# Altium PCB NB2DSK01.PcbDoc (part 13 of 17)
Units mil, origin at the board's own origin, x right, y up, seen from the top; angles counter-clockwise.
Board outline 11815 x 6500.03 mil, 8 copper layers (Top Layer, MidLayer1, MidLayer2, GND, PWR, MidLayer3, MidLayer4, Bottom Layer), stack 74.62 mil thick; 798 components, 1002 nets, 3927 pads, 3182 vias.
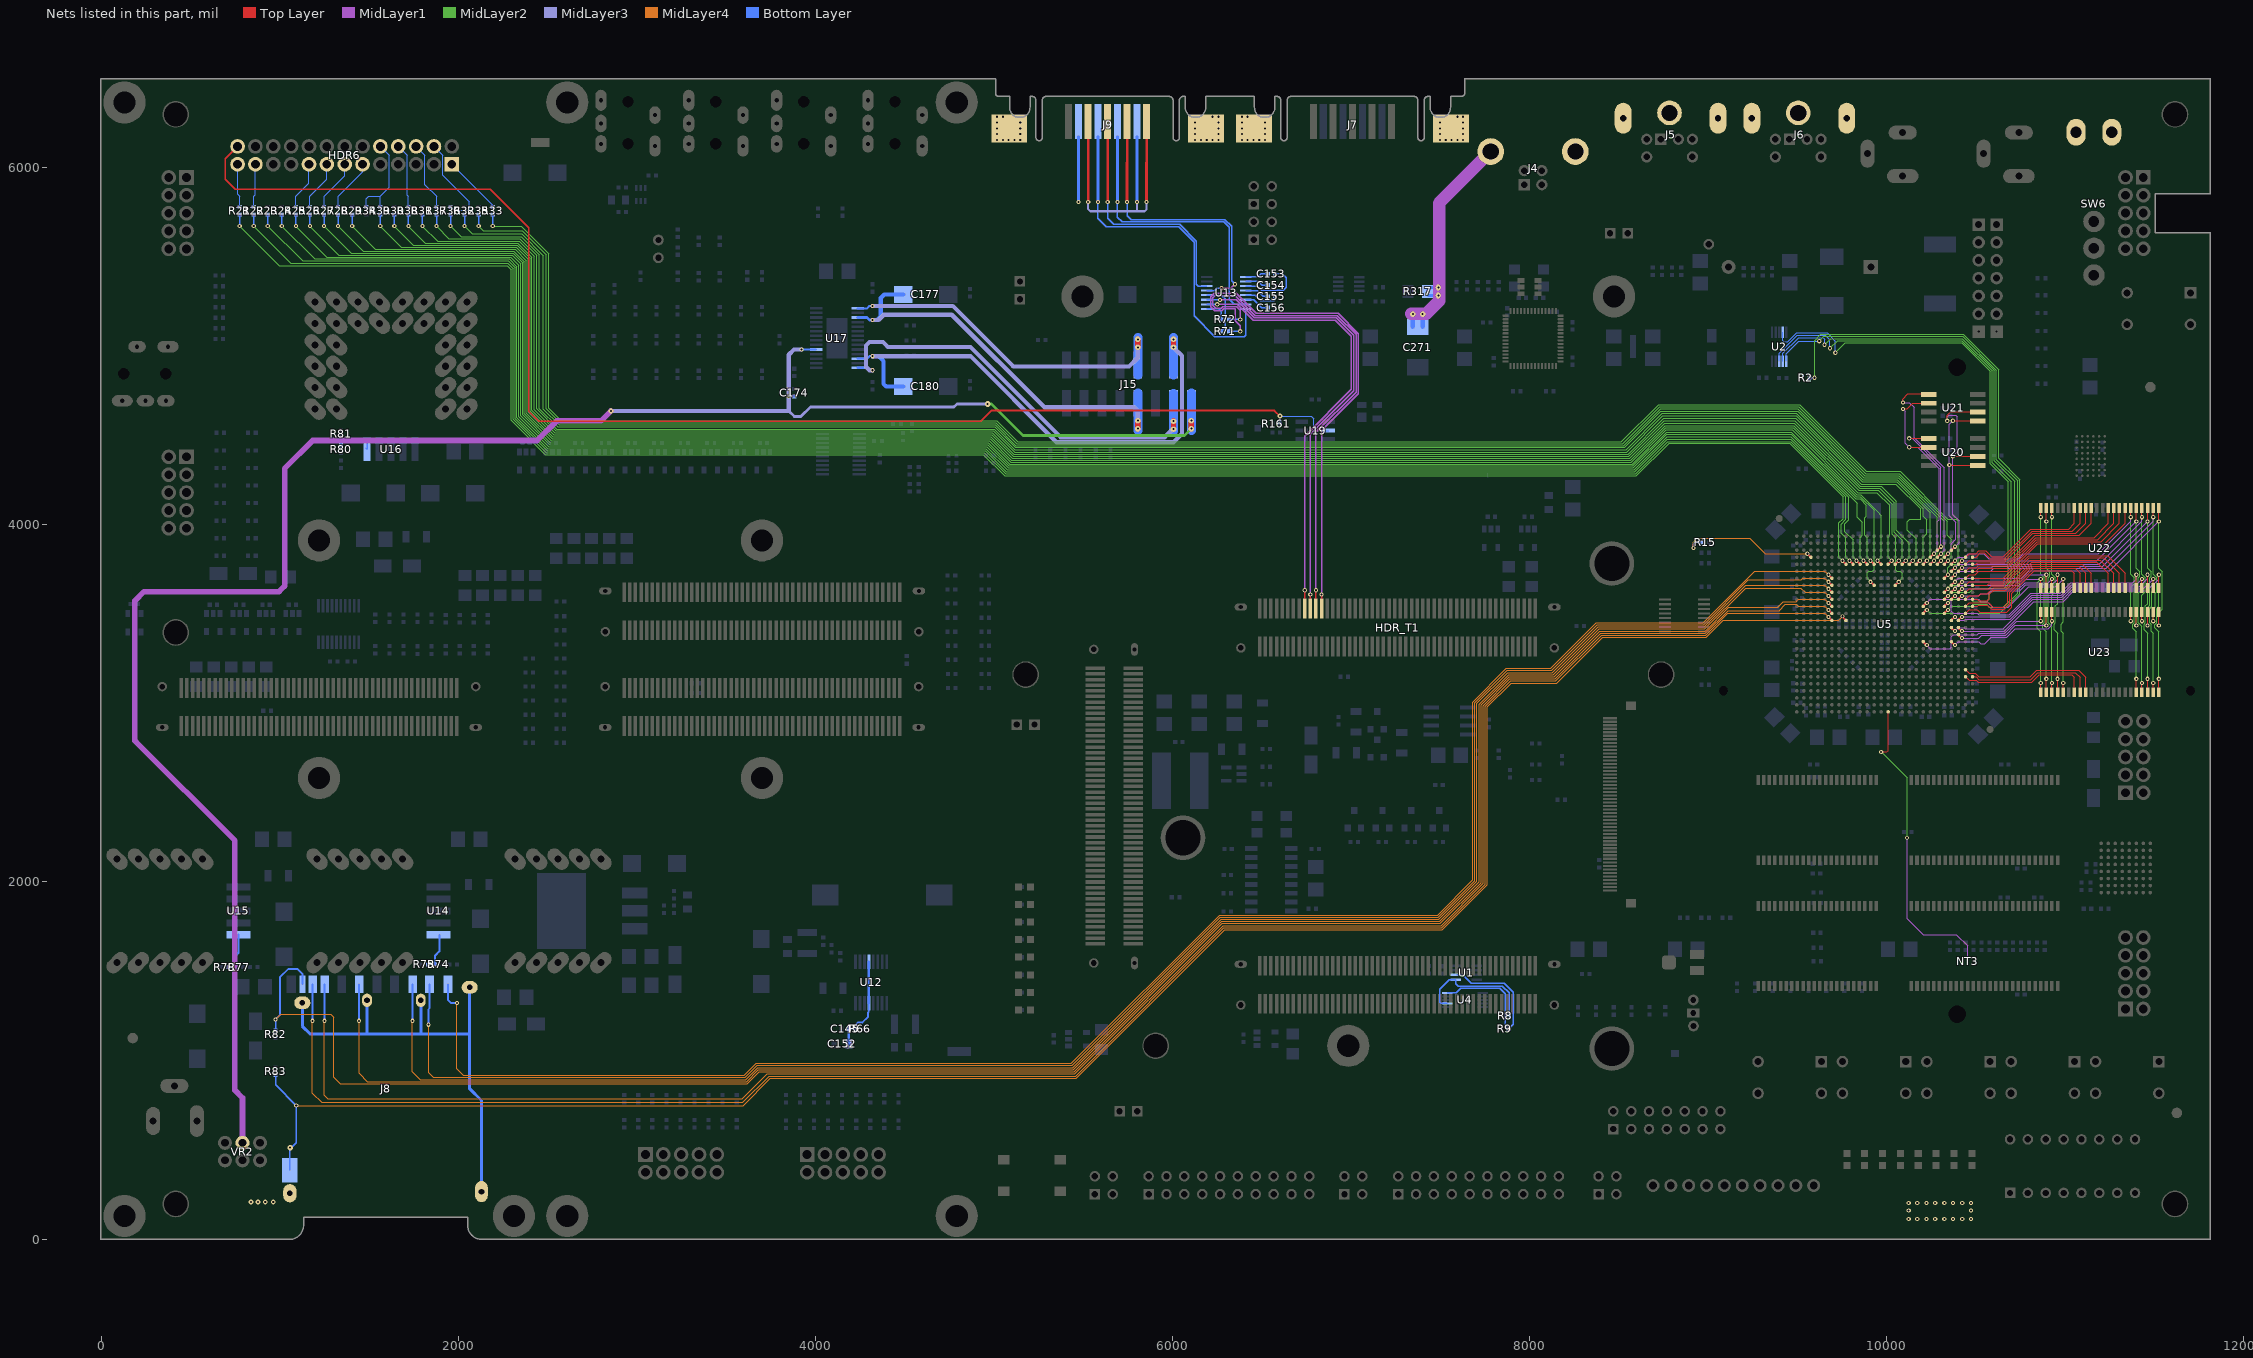
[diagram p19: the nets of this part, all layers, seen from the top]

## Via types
v1: diameter 23.62, hole 11.81, Top Layer to Bottom Layer, tented both sides, 1950 vias
v2: diameter 27.56, hole 11.81, Top Layer to Bottom Layer, tented both sides, 679 vias
v3: diameter 23.62, hole 11.81, Top Layer to Bottom Layer, 194 vias
v4: diameter 31.5, hole 11.81, Top Layer to Bottom Layer, tented both sides, 178 vias
v5: diameter 21.65, hole 11.81, Top Layer to Bottom Layer, tented both sides, 67 vias
v6: diameter 23.62, hole 11.81, Top Layer to Bottom Layer, tented bottom, 53 vias
v7: diameter 26, hole 11.81, Top Layer to Bottom Layer, tented both sides, 21 vias
v8: diameter 26, hole 11.81, Top Layer to Bottom Layer, 13 vias
v9: diameter 28, hole 11.81, Top Layer to Bottom Layer, 8 vias
v10: diameter 25.59, hole 11.81, Top Layer to Bottom Layer, tented both sides, 7 vias
v11: diameter 39.37, hole 11.81, Top Layer to Bottom Layer, tented both sides, 5 vias
v12: diameter 30, hole 11.81, Top Layer to Bottom Layer, 3 vias
v13: diameter 30, hole 11.81, Top Layer to Bottom Layer, tented both sides, 2 vias
v14: diameter 23, hole 11.81, Top Layer to Bottom Layer, tented both sides, 1 vias
v15: diameter 26.56, hole 11.81, Top Layer to Bottom Layer, tented both sides, 1 vias

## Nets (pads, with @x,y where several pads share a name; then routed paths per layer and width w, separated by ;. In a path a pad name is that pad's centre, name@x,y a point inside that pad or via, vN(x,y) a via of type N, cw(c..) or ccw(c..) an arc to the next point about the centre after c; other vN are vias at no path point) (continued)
PPRT#.D4: HDR6.6 R28.2 | length 295.4
  Bottom Layer w5: R28.2@1326.77,5781.02 1326.77,5840.55 1463.78,5977.56 HDR6.6@1463.78,6019.69
PPRT#.D5: HDR6.7 R27.2 | length 286.6
  Bottom Layer w5: R27.2@1248.03,5781.02 1248.03,5840.55 1363.78,5956.3 HDR6.7@1363.78,6019.69
PPRT#.D6: HDR6.8 R26.2 | length 277.8
  Bottom Layer w5: R26.2@1169.29,5781.02 1169.29,5840.55 1263.78,5935.04 HDR6.8@1263.78,6019.69
PPRT#.D7: HDR6.9 R25.2 | length 269
  Bottom Layer w5: R25.2@1090.55,5781.02 1090.55,5840.55 1163.78,5913.78 HDR6.9@1163.78,6019.69
PPRT#.DETECT: HDR6.18 R34.1 R39.2 | length 511.3
  Bottom Layer w5: R34.1@1484.25,5781.02 1484.25,5827.65 1497.15,5840.55 1562.99,5840.55 ; R39.2@1562.99,5781.02 1562.99,5840.55 ; HDR6.18@1563.78,6119.69 1613.94,6069.52 1613.94,5891.5 1562.99,5840.55
PPRT#.ERROR: HDR6.15 R36.1 | length 550.7
  Bottom Layer w5: HDR6.15@1863.78,6119.69 1913.9,6069.57 1913.9,5958.6 2062.1,5810.4 2062.1,5767.9 2054.9,5760.7 1977.02,5760.7 R36.1@1956.69,5781.02
PPRT#.INIT: HDR6.16 R37.2 | length 386
  Bottom Layer w5: HDR6.16@1763.78,6119.69 1812.9,6070.57 1812.9,5905.6 1877.95,5840.55 R37.2@1877.95,5781.02
PPRT#.ONE_WIRE_P: HDR6.26 R161.2 U19.2 | length 7699.6
  Top Layer w10: HDR6.26@763.78,6119.69 695,6050.91 695,5935 750,5880 2180,5880 2395,5665 2395,4635 2450,4580 4925.6,4580 4985.8,4640.2 6570.76,4640.2 v2(6601.98,4608.98)
  Bottom Layer w5: R161.2@6601.98,4567.47 v2(6601.98,4608.98) 6776.02,4608.98 6792,4593 6792,4542 6805.47,4528.53 U19.2@6874.27,4528.53
PPRT#.PE: HDR6.12 R22.1 | length 247.2
  Bottom Layer w5: R22.1@854.33,5781.02 854.33,5840.55 863.78,5850 HDR6.12@863.78,6019.69
  Bottom Layer w7.87: R22.1@854.33,5776.38 R22.1@854.33,5781.02
PPRT#.SELECT: HDR6.17 R38.2 | length 362.5
  Bottom Layer w5: HDR6.17@1663.78,6119.69 1713.94,6069.52 1713.94,5847.08 1720.47,5840.55 R38.2@1720.47,5781.02
  Bottom Layer w7.87: R38.2@1727.56,5780.71 R38.2@1727.56,5781.02
PPRT#.SELECTIN: HDR6.13 R21.1 | length 247.4
  Bottom Layer w5: HDR6.13@763.78,6019.69 763.78,5852.36 775.59,5840.55 R21.1@775.59,5781.02 R21.1@775.59,5777.17
PPRT#.STROBE: HDR6.1 R33.2 | length 333.6
  Bottom Layer w5: HDR6.1@1963.78,6019.69 2192.91,5790.55 R33.2@2192.91,5781.02
PPRT.ACK: R24.2 U5.E11 | length 10553.6
  Top Layer w7.87: v1(9870.08,3799.21) U5.E11@9889.76,3779.53
  MidLayer2 w5: v1(1011.81,5673.23) 1195.88,5489.16 2191.94,5489.16 2285.97,5489.16 2328.68,5446.45 2328.68,4600.46 2502.03,4427.11 4954.78,4427.11 5074.37,4307.52 8584.74,4307.52 8770.68,4493.45 9463.47,4493.45 9834.65,4122.28 9834.65,4043.31 9862.2,4015.75 9862.2,4000 9862.2,3940.95 9850.39,3929.13 9850.39,3818.9 v1(9870.08,3799.21)
  Bottom Layer w7.87: v1@1011.81,5677.17 R24.2@1011.81,5738.66 R24.2@1011.81,5740.55
PPRT.AUTOFD: R35.1 U5.E22 | length 9913.7
  Top Layer w7.87: U5.E22@10322.83,3779.53 v1(10342.52,3799.21)
  MidLayer2 w5: v1(2114.17,5673.23) 2139.95,5647.45 2357.68,5647.45 2492.68,5512.45 2492.68,4650.45 2570.68,4572.45 5010.22,4572.45 5128.51,4454.16 8521.39,4454.16 8728.68,4661.45 9507.49,4661.45 9881.54,4287.4 10070.87,4287.4 10338.58,4019.69 10338.58,3942.74 10362.2,3919.12 10362.2,3818.9 v1(10342.52,3799.21)
  Bottom Layer w7.87: v1@2114.17,5677.17 R35.1@2114.17,5738.66
PPRT.BUSY: R23.2 U5.E10 | length 10613.5
  Top Layer w7.87: v1(9830.71,3799.21) U5.E10@9850.39,3779.53
  MidLayer2 w5: v1(933.07,5673.23) 1128.3,5478 2279.13,5478 2317.68,5439.45 2317.68,4595.71 2497.41,4415.97 4950.17,4415.97 5069.76,4296.38 8588.61,4296.38 8771.68,4479.45 9463.33,4479.45 9787.4,4155.38 9787.4,4029.03 9764.68,4006.31 9764.68,3962.39 9811.02,3916.05 9811.02,3818.9 v1(9830.71,3799.21)
  Bottom Layer w7.87: v1@933.07,5677.17 R23.2@933.07,5738.66 R23.2@933.07,5740.95
PPRT.D0: R32.1 U5.E21 | length 9964.4
  Top Layer w7.87: U5.E21@10283.46,3779.53 v1(10303.15,3799.21)
  MidLayer2 w5: v1(2035.43,5673.23) 2079.21,5629.45 2354.68,5629.45 2476.68,5507.45 2476.68,4648.45 2564.68,4560.45 5006.48,4560.45 5122.77,4444.16 8527.39,4444.16 8733.68,4650.45 9501.78,4650.45 9876.65,4275.59 10066.93,4275.59 10322.83,4019.69 10322.83,4015.75 10322.83,4000 10322.83,3818.9 v1(10303.15,3799.21)
  Bottom Layer w7.87: v1@2035.43,5677.17 R32.1@2035.43,5738.66
PPRT.D1: R31.1 U5.E18 | length 10139.2
  Top Layer w7.87: U5.E18@10165.35,3779.53 v1(10185.04,3799.21)
  MidLayer2 w5: v1(1799.21,5673.23) 1884.11,5588.33 2341.8,5588.33 2426.68,5503.45 2426.68,4645.45 2545.31,4526.82 4996.08,4526.82 5115.67,4407.23 8543.46,4407.23 8746.68,4610.45 9491.68,4610.45 9861.97,4240.16 10055.12,4240.16 10204.72,4090.55 10204.72,4048.74 10223.68,4029.79 10223.68,3950.9 10204.72,3931.94 10204.72,3818.9 v1(10185.04,3799.21)
  Bottom Layer w7.87: v1@1799.21,5677.17 R31.1@1799.21,5738.66 R31.1@1799.21,5741.34
PPRT.D2: R30.1 U5.E16 | length 10176.1
  Top Layer w7.87: U5.E16@10086.61,3779.53 v1(10106.3,3799.21)
  MidLayer2 w5: v1(1641.73,5673.23) 1748.39,5566.57 2329.57,5566.57 2401.74,5494.39 2401.74,4637.63 2534.31,4505.06 4987.07,4505.06 5106.66,4385.47 8554.69,4385.47 8752.68,4583.45 9485.27,4583.45 9852.19,4216.54 9968.5,4216.54 10052.68,4132.36 10052.68,3969.18 10111.8,3910.06 10125.98,3895.87 10125.98,3818.9 v1(10106.3,3799.21)
  Bottom Layer w7.87: v1@1641.73,5677.17 R30.1@1641.73,5738.66
PPRT.D3: R29.1 U5.H15 | length 10497.1
  Top Layer w7.87: U5.H15@10047.24,3661.42 v1(10066.93,3681.1)
  MidLayer2 w5: v1(1405.51,5673.23) 1534.44,5544.3 2317.84,5544.3 2381.68,5480.45 2381.68,4626.19 2525.09,4482.79 4977.84,4482.79 5097.43,4363.19 8566.42,4363.19 8758.68,4555.45 9479.86,4555.45 9842.4,4192.91 9952.76,4192.91 10029.68,4115.99 10029.68,3946.91 10047.24,3929.35 10047.25,3748.68 10047.25,3747.64 10054.72,3740.16 10075.59,3740.16 10086.68,3729.07 10086.68,3700.85 v1(10066.93,3681.1)
  Bottom Layer w7.87: v1@1405.51,5677.17 R29.1@1405.51,5738.66
PPRT.D4: R28.1 U5.E14 | length 10409
  Top Layer w7.87: U5.E14@10007.87,3779.53 v1(10027.56,3799.21)
  MidLayer2 w5: v1(1326.77,5673.23) 1466.84,5533.16 2311.09,5533.16 2370.68,5473.57 2370.68,4621.44 2520.48,4471.65 4973.23,4471.65 5092.82,4352.06 8570.29,4352.06 8761.68,4543.45 9475.16,4543.45 9837.51,4181.1 9944.88,4181.1 10015.75,4110.24 10015.75,3945.9 10007.87,3938.03 10007.87,3818.9 v1(10027.56,3799.21)
  Bottom Layer w7.87: v1@1326.77,5677.17 R28.1@1326.77,5738.66 R28.1@1326.77,5741.73
PPRT.D5: R27.1 U5.E13 | length 10401
  Top Layer w7.87: v1(9948.82,3799.21) U5.E13@9968.5,3779.53
  MidLayer2 w5: v1(1248.03,5673.23) 1399.23,5522.03 2307.11,5522.03 2359.74,5469.39 2359.74,4616.64 2515.86,4460.51 4968.62,4460.51 5088.21,4340.92 8573.51,4340.92 8764.04,4531.45 9470.46,4531.45 9832.62,4169.29 9855.06,4169.29 9960.63,4063.72 9960.63,4058.85 9968.5,4050.98 9968.5,4015.75 9968.5,4000 9968.5,3818.9 v1(9948.82,3799.21)
  Bottom Layer w7.87: v1@1248.03,5677.17 R27.1@1248.03,5737.8
PPRT.D6: R26.1 U5.H12 | length 10629
  Top Layer w7.87: v1(9909.45,3681.1) U5.H12@9929.13,3661.42
  MidLayer2 w5: v1(1169.29,5673.23) 1331.63,5510.89 2301.24,5510.89 2349.74,5462.39 2349.74,4610.89 2511.25,4449.38 4964.01,4449.38 5083.6,4329.79 8577.02,4329.79 8766.68,4519.45 9465.75,4519.45 9827.73,4157.48 9852.72,4157.48 9929.13,4081.07 9929.13,3972.44 ; v1(9909.45,3681.1) 9889.76,3700.79 9889.76,3731.1 9898.82,3740.16 9920.08,3740.16 9929.13,3749.21 9929.13,3750.38 9929.13,4000
  Bottom Layer w7.87: v1@1169.29,5677.17 R26.1@1169.29,5738.66
PPRT.D7: R25.1 U5.E12 | length 10511.8
  Top Layer w7.87: v1(9909.45,3799.21) U5.E12@9929.13,3779.53
  MidLayer2 w5: v1(1090.55,5673.23) 1264.03,5499.75 2293.38,5499.75 2339.68,5453.45 2339.68,4605.2 2506.64,4438.24 4959.39,4438.24 5078.98,4318.65 8580.88,4318.65 8768.68,4506.45 9464.61,4506.45 9825.4,4145.67 9850.39,4145.67 9885.83,4110.24 9885.83,4047.24 9877.95,4039.37 9877.95,4015.75 9877.95,4000 9877.95,3940.95 9889.76,3929.13 9889.76,3818.9 v1(9909.45,3799.21)
  Bottom Layer w7.87: v1@1090.55,5677.17 R25.1@1090.55,5738.66
PPRT.ERROR: R36.2 U5.E20 | length 10019.2
  Top Layer w7.87: U5.E20@10244.09,3779.53 v1(10263.78,3799.21)
  MidLayer2 w5: v1(1956.69,5673.23) 2015.47,5614.45 2352.68,5614.45 2453.8,5513.33 2453.8,4651.33 2556.68,4548.45 5003.98,4548.45 5118.97,4433.45 8532.68,4433.45 8734.68,4635.45 9500.08,4635.45 9871.76,4263.78 10062.99,4263.78 10283.46,4043.31 10283.46,4015.75 10283.46,4000 10283.46,3818.9 v1(10263.78,3799.21)
  Bottom Layer w7.87: v1@1956.69,5677.17 R36.2@1956.69,5738.66 R36.2@1956.69,5742.13
PPRT.INIT: R37.1 U5.E19 | length 10071.4
  Top Layer w7.87: U5.E19@10204.72,3779.53 v1(10224.41,3799.21)
  MidLayer2 w5: v1(1877.95,5673.23) 1947.73,5603.45 2344.68,5603.45 2438.68,5509.45 2438.68,4649.45 2551.32,4536.82 5000.22,4536.82 5116.59,4420.45 8539.68,4420.45 8743.68,4624.45 9494.38,4624.45 9866.87,4251.97 10059.06,4251.97 10244.09,4066.93 10244.09,4015.75 10244.09,4000 10244.09,3818.9 v1(10224.41,3799.21)
  Bottom Layer w7.87: v1@1877.95,5677.17 R37.1@1877.95,5738.66 R37.1@1877.95,5740.55
PPRT.PE: R22.2 U5.E9 | length 10658.3
  Top Layer w7.87: v1(9791.34,3799.21) U5.E9@9811.02,3779.53
  MidLayer2 w5: v1(854.33,5673.23) 1062.11,5465.45 2276.68,5465.45 2306.68,5435.45 2306.68,4590.96 2492.8,4404.84 4945.56,4404.84 5065.15,4285.25 8593.47,4285.25 8774.68,4466.45 9462.19,4466.45 9771.65,4156.99 9771.65,4030.43 9745.68,4004.45 9745.68,3954.45 9771.65,3928.48 9771.65,3818.9 v1(9791.34,3799.21)
  Bottom Layer w7.87: v1@854.33,5677.17 R22.2@854.33,5730.04
PPRT.PLUG: R39.1 U5.E15 | length 10228.1
  Top Layer w7.87: U5.E15@10047.24,3779.53 v1(10066.93,3799.21)
  MidLayer2 w5: v1(1562.99,5673.23) 1680.79,5555.43 2323.7,5555.43 2391.74,5487.39 2391.74,4631.88 2529.7,4493.92 4982.46,4493.92 5102.05,4374.33 8560.56,4374.33 8755.68,4569.45 9482.56,4569.45 9847.3,4204.73 9960.63,4204.73 10041.68,4123.68 10041.68,3959.45 10086.61,3914.52 10086.61,3818.9 v1(10066.93,3799.21)
  Bottom Layer w7.87: v1@1562.99,5677.17 R39.1@1562.99,5738.66 1562.99,5741.73 R39.1@1563.78,5742.52
PPRT.SELECT: R38.1 U5.E17 | length 10273.3
  Top Layer w7.87: U5.E17@10125.98,3779.53 v1(10145.67,3799.21)
  MidLayer2 w5: v1(1720.47,5673.23) 1816,5577.7 2333.43,5577.7 2411.74,5499.39 2411.74,4643.37 2538.93,4516.19 4991.68,4516.19 5111.27,4396.6 8550.83,4396.6 8750.68,4596.45 9488.97,4596.45 9857.08,4228.35 10051.18,4228.35 10188.98,4090.55 10188.98,4030.62 10129.35,4030.62 10115.95,4017.22 10115.95,3970.67 10165.35,3921.26 10165.35,3818.9 v1(10145.67,3799.21)
  Bottom Layer w7.87: v1@1720.47,5677.17 R38.1@1720.47,5738.66 R38.1@1720.47,5746.46
PPRT.SELECTIN: R21.2 U5.E8 | length 10718.6
  Top Layer w7.87: v1(9751.97,3799.21) U5.E8@9771.65,3779.53
  MidLayer2 w5: v1(775.59,5673.23) 998.37,5450.45 2273.68,5450.45 2295.68,5428.45 2295.68,4586.21 2488.19,4393.7 4940.94,4393.7 5060.53,4274.11 8598.23,4274.11 8780.57,4456.45 9458.04,4456.45 9755.68,4158.82 9755.68,4035.45 9732.28,4012.06 9732.28,3818.9 v1(9751.97,3799.21)
  Bottom Layer w7.87: v1@775.59,5677.17 R21.2@775.59,5738.66
PPRT.STROBE: R33.1 U5.G22 | length 10007.3
  Top Layer w7.87: U5.G22@10322.83,3700.79 v1(10342.52,3720.47)
  MidLayer2 w5: v1(2192.91,5673.23) 2351.91,5673.23 2506.68,5518.45 2506.68,4654.45 2577.68,4583.45 5014.97,4583.45 5133.88,4464.54 8513.77,4464.54 8721.68,4672.45 9513.19,4672.45 9886.43,4299.21 10074.8,4299.21 10342.52,4031.5 10389.76,4031.5 10401.57,4019.69 10401.57,4003.94 10401.57,3787.4 10393.7,3779.53 10362.2,3779.53 10342.52,3759.84 v1(10342.52,3720.47)
  Bottom Layer w7.87: v1@2192.91,5677.17 R33.1@2192.91,5738.66 R33.1@2192.91,5742.52
PROG_B: R15.1 U5.D3 | length 815.2
  Top Layer w7.87: v1(9555.12,3838.58) U5.D3@9574.8,3818.9
  MidLayer4 w5: v1(8916.9,3870.9) 8916.9,3902.77 8939.32,3925.2 9232,3925.2 9318.61,3838.58 v1(9555.12,3838.58)
  Bottom Layer w5: v1(8916.9,3870.9) 8916.9,3894.7 8924.27,3902.07 R15.1@8962.1,3902.07
PWMVCCA: C145.1 C152.2 R66.1 U12.5 U12.12 | length 545.9
  Bottom Layer w10: R66.1@4229.5,1178.45 4229.5,1204.27 4238.68,1213.45 4263.68,1213.45 4293.68,1243.45 4293.68,1268.45 4299.18,1273.95 U12.5@4299.18,1321.45
  Bottom Layer w15: C152.2@4186.35,1094.18 C145.1@4186.35,1178.45 R66.1@4229.5,1178.45 ; U12.5@4299.18,1321.45 U12.12@4299.18,1553.45
REF_1V8: R74.2 R75.2 U14.5 | length 214.7
  Bottom Layer w8: R75.2@1829.86,1538.45 R74.2@1869.65,1538.45
  Bottom Layer w11.81: R74.2@1869.65,1538.45 1869.65,1587.71 1893.68,1611.75 U14.5@1893.68,1703.45
REF_2V5: R77.2 R78.1 U15.5 | length 220.5
  Bottom Layer w8: R78.1@719.86,1523.45 R77.2@752.5,1523.45
  Bottom Layer w11.81: R77.2@752.5,1523.45 752.5,1587.27 768.68,1603.45 U15.5@768.68,1704.6
REF_3V3: R80.1 R81.2 U16.5 | length 244.6
  Bottom Layer w10: R80.1@1343.68,4446.03 1343.68,4468.3 ; R80.1@1343.68,4451.03 R80.1@1344,4446.05 ; R81.2@1343.68,4488.67 1343.68,4468.3 ; R80.1@1344,4446.03 R80.1@1344.26,4441.85 ; U16.5@1483.64,4429.63 U16.5@1489.82,4423.45 1489.82,4456.38 1477.9,4468.3 1343.68,4468.3
RS232#.CTS: J9.8 U13.8 | length 1951.8
  Bottom Layer w7.87: v1(5582.15,5807.92) 5582.15,5716.95 5628.15,5670.95 6033.73,5670.95 6121.02,5583.67 6121.02,5171.18 6237.5,5054.7 6402.7,5054.7 6411.09,5063.09 U13.8@6411.09,5209.65
  Bottom Layer w15.75: v1(5582.15,5807.92) J9.8@5582.14,6173.81
RS232#.DCD: J9.1 J9.4 J9.6 | length 1735.7
  Top Layer w15.75: J9.4@5527.53,6258.86 v1(5527.62,5807.92) ; v1(5854.79,5807.92) J9.1@5855.29,6258.86
  MidLayer3 w11.81: v1(5527.62,5807.92) 5527.62,5768.38 5539.74,5756.26 5842.66,5756.26 5854.79,5768.38 v1(5854.79,5807.92) ; 5800.26,5756.26 v1(5800.26,5807.92)
  Bottom Layer w15.75: v1(5800.26,5807.92) J9.6@5800.25,6173.81
RS232#.RI: J9.9 | length 365.9
  Bottom Layer w15.75: v1(5473.09,5807.92) J9.9@5473.08,6173.81
RS232#.RTS: J9.7 U13.7 | length 1608.2
  Bottom Layer w7.87: v1(5691.2,5807.92) 5691.2,5722.9 5717.4,5696.7 6287.4,5696.7 6318.2,5665.9 6318.2,5264 6346.96,5235.24 U13.7@6411.09,5235.24
  Bottom Layer w15.75: v1(5691.2,5807.92) J9.7@5691.19,6173.81
RS232#.RXD: J9.2 U13.13 | length 1640.2
  Top Layer w15.75: v1(5745.73,5807.92) J9.2@5746.03,6258.87
  MidLayer1 w7.87: v1(6274.3,5325.1) 6327.29,5325.1 v1(6349.57,5347.38)
  Bottom Layer w7.87: v1(5745.73,5807.92) 5745.73,5732.57 5768.73,5709.57 6292.73,5709.57 6331.07,5671.23 6331.07,5365.88 v1(6349.57,5347.38) ; U13.13@6192.59,5312.01 6233.61,5312.01 6246.7,5325.1 v1(6274.3,5325.1)
RS232#.TXD: J9.3 U13.14 | length 1395.3
  Top Layer w15.75: v1(5636.68,5807.92) J9.3@5636.78,6258.87
  Bottom Layer w7.87: v1(5636.68,5807.92) 5636.68,5718.42 5671.27,5683.83 6039.07,5683.83 6133.89,5589 6133.89,5347.9 6144.19,5337.6 U13.14@6192.59,5337.6
RS232.CTS: HDR_T1.22 R72.1 | length 2852.1
  Top Layer w7.87: HDR_T1.22@6803.15,3531.5 v1(6803.15,3633.86)
  MidLayer1 w7.87: v1(6379,5150.61) 6379,5201.63 6358.26,5222.36 6280.36,5222.36 6272,5214 6241,5214 6226,5229 6226,5271 6238,5283 6352.25,5283 6463.5,5171.75 6922.37,5171.75 7027.75,5066.37 7027.75,4742.04 6803.15,4517.44 v1(6803.15,3633.86)
  Bottom Layer w7.87: R72.1@6315.54,5150.61 v1(6379,5150.61)
RS232.RTS: HDR_T1.18 U13.10 | length 2516.4
  Top Layer w7.87: HDR_T1.18@6740.16,3531.5 v1(6740.16,3633.86)
  MidLayer1 w7.87: v1(6250.66,5235.24) 6363.6,5235.24 6452.83,5146 6911.71,5146 7002,5055.71 7002,4758.96 6740.16,4497.11 v1(6740.16,3633.86)
  Bottom Layer w7.87: U13.10@6192.59,5235.24 v1(6250.66,5235.24)
RS232.RXD: HDR_T1.24 R71.1 | length 2959.3
  Top Layer w7.87: HDR_T1.24@6834.65,3531.5 v1(6834.64,3610.24)
  MidLayer1 w7.87: v1(6379,5084) 6379,5116 6351,5144 6351,5206.36 6347.87,5209.49 6285.7,5209.49 6275.21,5199 6237,5199 6213,5223 6213,5277 6232.49,5296.49 6356.96,5296.49 6468.83,5184.62 6927.7,5184.62 7040.62,5071.7 7040.62,4735.08 6834.64,4529.1 v1(6834.64,3610.24)
  Bottom Layer w7.87: R71.1@6315.54,5084 v1(6379,5084)
RS232.TXD: HDR_T1.20 U13.11 | length 2533.9
  Top Layer w7.87: HDR_T1.20@6771.65,3531.5 v1(6771.65,3610.24)
  MidLayer1 w7.87: v1(6266.22,5259.84) 6357.2,5259.84 6458.17,5158.87 6917.04,5158.87 7014.87,5061.04 7014.87,4751 6771.65,4507.78 v1(6771.65,3610.24)
  Bottom Layer w7.87: U13.11@6192.59,5260.83 v1@6265.24,5260.83
RS232_C1+: C153.1 U13.1 | length 129
  Bottom Layer w7.87: U13.1@6411.09,5388.78 6480.78,5388.78 6497.51,5405.51 C153.1@6533.14,5405.51
RS232_C1-: C153.2 U13.3 | length 364.8
  Bottom Layer w7.87: U13.3@6411.09,5337.6 6477.52,5337.6 6500.45,5314.67 6620.22,5314.67 6636.38,5330.82 6636.38,5382.83 6613.69,5405.51 C153.2@6574.48,5405.51
RS232_C2+: C155.1 U13.4 | length 135.5
  Bottom Layer w7.87: U13.4@6411.09,5312.01 6474.87,5312.01 6507.35,5279.53 C155.1@6533.14,5279.53
RS232_C2-: C155.2 U13.5 | length 203.6
  Bottom Layer w7.87: U13.5@6411.09,5286.42 6462.28,5286.42 6493.18,5255.51 6566.8,5255.51 6574.48,5263.19 C155.2@6574.48,5279.53 C155.2@6574.48,5287.4
RS232_CTS#: R72.2 U13.9 | length 139
  Bottom Layer w7.87: U13.9@6192.59,5209.65 6258.73,5209.65 6273.17,5195.2 R72.2@6273.17,5150.61 R72.2@6278.69,5145.09
RS232_RX#: R71.2 U13.12 | length 300.2
  Bottom Layer w7.87: U13.12@6192.59,5286.42 6273,5286.42 6294,5265.42 6294,5104.83 R71.2@6273.17,5084
RS232_V+: C154.2 U13.2 | length 130.6
  Bottom Layer w7.87: U13.2@6411.09,5363.19 6482.16,5363.19 6502.83,5342.52 C154.2@6533.14,5342.52
RS232_V-: C156.1 U13.6 | length 140.4
  Bottom Layer w7.87: U13.6@6411.09,5260.83 6455.39,5260.83 6499.68,5216.54 C156.1@6533.14,5216.54
RTC.CS_N: U2.4 U5.J22 | length 3003.6
  Top Layer w7.87: U5.J22@10322.83,3622.05 v1(10342.52,3641.73)
  MidLayer2 w5: v1(9712,4964) 9767.69,5019.69 10419,5019.69 10578.74,4859.95 10578.74,4342.63 10679.68,4241.69 10679.68,3687.56 10653.54,3661.42 10555.12,3661.42 10543.31,3661.42 10362.21,3661.42 v1(10342.52,3641.73)
  Bottom Layer w5: U2.4@9417.34,5078.18 9416.36,5077.19 9416.36,5030.93 9421.28,5026.01 9445.89,5026.01 9494.87,5075 9665.55,5075 9712,5028.55 v1(9712,4964)
RTC.DIN: U2.6 U5.M22 | length 3105.2
  Top Layer w7.87: U5.M22@10322.83,3503.94 v1(10342.52,3523.62)
  MidLayer2 w5: v1(9622,5029) 9648.12,5055.12 10425.99,5055.12 10614.17,4866.94 10614.17,4364.96 10732.28,4246.85 10732.28,3618.11 10653.54,3539.37 10574.8,3539.37 10559.06,3555.12 10543.31,3555.12 10484.25,3555.12 10472.44,3543.31 10362.21,3543.31 v1(10342.52,3523.62)
  Bottom Layer w5: U2.6@9437.03,4916.76 9437.03,4959.8 9506.23,5029 v1(9622,5029)
RTC.DOUT: U2.7 U5.L22 | length 3094.3
  Top Layer w7.87: U5.L22@10322.83,3543.31 v1(10342.52,3562.99)
  MidLayer2 w5: v1(9652,5009) 9686.31,5043.31 10423.66,5043.31 10602.36,4864.61 10602.36,4357.77 10715.68,4244.45 10715.68,3684.19 10661.42,3629.92 10586.61,3629.92 10574.8,3618.11 10574.8,3586.61 10559.06,3570.87 10543.31,3570.87 10484.25,3570.87 10472.44,3582.68 10362.21,3582.68 v1(10342.52,3562.99)
  Bottom Layer w5: U2.7@9417.34,4916.76 9417.34,4960.11 9505.78,5048.55 9643,5048.55 9652,5039.55 v1(9652,5009)
RTC.RST_N: R2.1 U5.M19 | length 3295.4
  Top Layer w7.87: U5.M19@10204.72,3503.94 v1(10224.41,3523.62)
  MidLayer2 w5: v1(9595.89,4823.89) 9595.89,5032 9630.82,5066.93 10428.32,5066.93 10625.98,4869.27 10625.98,4372.15 10744.09,4254.04 10744.09,3614.17 10633.86,3503.94 10562.99,3503.94 10543.31,3503.94 ; v1(10224.41,3523.62) 10244.09,3503.94 10543.31,3503.94 ; 10515.75,3503.94 10543.31,3503.94
  Bottom Layer w5: R2.1@9568,4823.89 v1(9595.89,4823.89)
RTC.SCLK: U2.8 U5.K22 | length 3063.3
  Top Layer w7.87: U5.K22@10322.83,3582.68 v1(10342.52,3602.36)
  MidLayer2 w5: v1(9682,4989) 9724.5,5031.5 10421.33,5031.5 10590.55,4862.28 10590.55,4348.58 10697.68,4241.45 10697.68,3685.87 10657.48,3645.67 10555.12,3645.67 10543.31,3645.67 10488.19,3645.67 10464.57,3622.05 10362.21,3622.05 v1(10342.52,3602.36)
  Bottom Layer w5: U2.8@9397.66,4916.76 9397.66,4962.04 9497.62,5062 9655.87,5062 9682,5035.87 v1(9682,4989)
SCL: R8.2 U1.5 U4.2 | length 702.3
  Bottom Layer w7.87: U4.2@7539.38,1319.69 7504,1319.69 7496,1327.69 7496,1399.68 7550,1453.68 U1.5@7586.54,1453.68 7586.54,1429.46 7599,1417 7847,1417 7884.97,1379.03 R8.2@7884.97,1251.8
SD.CLK: J8.5 U5.K6 | length 10521.2
  Top Layer w7.87: v1(9673.23,3602.36) U5.K6@9692.91,3582.68
  MidLayer4 w5: v1(1444.09,1222.44) 1444.09,927.79 1489.99,881.89 3614.17,881.89 3681.1,948.82 5444.88,948.82 6275.59,1779.53 7496.06,1779.53 7716.54,2000 7716.54,2996.06 7881.89,3161.42 8132.79,3161.42 8388.69,3417.32 8979.75,3417.32 9208.88,3646.45 9518.9,3646.45 9543.31,3622.05 9653.54,3622.05 v1(9673.23,3602.36)
  Bottom Layer w10: v1(1444.09,1222.44) J8.5@1444.1,1426.11
SD.CMD: J8.2 U5.J6 | length 10203.6
  Top Layer w7.87: v1(9673.23,3641.73) U5.J6@9692.91,3622.05
  MidLayer4 w5: v1(1743.11,1222.44) 1743.11,936.09 1785.5,893.7 3610.24,893.7 3677.17,960.63 5440.95,960.63 6271.65,1791.34 7492.13,1791.34 7704.72,2003.94 7704.72,3000 7877.95,3173.23 8127.89,3173.23 8383.8,3429.13 8977.42,3429.13 9209.7,3661.42 9413.39,3661.42 9433.07,3661.42 9653.54,3661.42 v1(9673.23,3641.73)
  Bottom Layer w10: v1(1743.11,1222.44) J8.2@1743.11,1426.11
SD.DAT0: J8.7 U5.M6 | length 10822.8
  Top Layer w7.87: v1(9673.23,3523.62) U5.M6@9692.91,3503.94
  MidLayer4 w5: v1(1250.2,1222.44) 1250.2,805.3 1269.05,786.45 3590.68,786.45 3729.43,925.2 5452.76,925.2 6283.46,1755.91 7503.94,1755.91 7740.16,1992.13 7740.16,2988.19 7889.76,3137.8 8142.57,3137.8 8398.48,3393.7 8984.41,3393.7 9111.16,3520.45 9397.75,3520.45 9432.42,3555.12 9492.13,3555.12 9503.94,3543.31 9653.54,3543.31 v1(9673.23,3523.62)
  Bottom Layer w10: v1(1250.2,1222.44) J8.7@1250.2,1426.11
SD.DAT1: J8.8 U5.N6 | length 10874.2
  Top Layer w7.87: v1(9673.23,3484.25) U5.N6@9692.91,3464.57
  MidLayer4 w5: v1(1183.27,1222.44) 1183.27,817.07 1234.89,765.45 3592.22,765.45 3740.16,913.39 5456.69,913.39 6287.4,1744.1 7507.87,1744.1 7751.97,1988.19 7751.97,2984.25 7893.7,3125.99 8147.46,3125.99 8403.37,3381.89 8986.74,3381.89 9108.79,3503.94 9413.39,3503.94 9433.07,3503.94 9653.54,3503.94 v1(9673.23,3484.25)
  Bottom Layer w10: v1(1183.27,1222.44) J8.8@1183.27,1426.11
SD.DAT2: J8.9 U5.G6 | length 10000.1
  Top Layer w7.87: v1(9673.23,3720.47) U5.G6@9692.91,3700.79
  MidLayer4 w5: v1(1992.27,1323.05) 1992.27,952.97 2027.92,917.32 3602.36,917.32 3669.29,984.25 5433.07,984.25 6263.78,1814.96 7484.25,1814.96 7681.1,2011.81 7681.1,3007.87 7870.08,3196.85 8118.11,3196.85 8374.02,3452.76 8972.76,3452.76 9260.16,3740.16 9413.39,3740.16 9433.07,3740.16 9653.54,3740.16 v1(9673.23,3720.47)
  Bottom Layer w10: J8.9@1941.52,1427.67 1941.52,1339.82 1958.28,1323.05 v1(1992.27,1323.05)
SD.DAT3: J8.1 U5.H6 | length 10126.4
  Top Layer w7.87: v1(9673.23,3681.1) U5.H6@9692.91,3661.42
  MidLayer4 w5: v1(1833.09,1200.91) 1833.09,932.49 1860.07,905.51 3606.3,905.51 3673.23,972.44 5437.01,972.44 6267.72,1803.15 7488.19,1803.15 7692.91,2007.87 7692.91,3003.94 7874.02,3185.04 8123,3185.04 8378.91,3440.95 8975.09,3440.95 9225.6,3691.45 9521,3691.45 9530.34,3700.79 9653.54,3700.79 v1(9673.23,3681.1)
  Bottom Layer w10: v1(1833.09,1200.91) 1833.1,1287.87 1839.35,1294.12 J8.1@1839.35,1427.67
SD.DETECT: J8.CD R82.2 U5.L6 | length 11332.2
  Top Layer w7.87: v1(9673.23,3562.99) U5.L6@9692.91,3543.31
  MidLayer4 w5: v1(976.38,1230.32) 1005.91,1259.84 1124.02,1259.84 ; 1125,1259.84 1285.43,1259.84 1303.15,1242.13 1303.15,905.22 1338.29,870.08 3618.11,870.08 3685.04,937.01 5448.82,937.01 6279.53,1767.72 7500,1767.72 7728.35,1996.06 7728.35,2992.13 7885.83,3149.61 8137.68,3149.61 8393.59,3405.51 8982.08,3405.51 9116.02,3539.45 9388.68,3539.45 9420.09,3570.87 9492.13,3570.87 9503.94,3582.68 9653.54,3582.68 v1(9673.23,3562.99)
  Bottom Layer w8: R82.2@976.38,1168.82 v1(976.38,1230.32)
  Bottom Layer w10: v1(976.38,1230.32) 1001,1254.94 1001,1465.45 1049,1513.45 1098.68,1513.45 1127.74,1484.4 J8.CD@1127.74,1427.67
SD.PROTECT: J8.WP R83.2 U5.N8 | length 11006.4
  Top Layer w7.87: v5@9751.97,3484.25 U5.N8@9771.65,3464.57
  MidLayer4 w5: v1(1092.52,748.03) 3594.49,748.03 3748.03,901.58 5460.63,901.58 6291.34,1732.28 7511.81,1732.28 7763.78,1984.25 7763.78,2980.32 7897.64,3114.17 8152.36,3114.17 8408.26,3370.08 8989.08,3370.08 9083.56,3464.57 9413.39,3464.57 9433.07,3464.57 9732.28,3464.57 v5@9751.97,3486.61
  Bottom Layer w7.87: R83.2@976.38,922.84 R83.2@976.38,919.76 976.38,864.17 v1(1092.52,748.03) 1092.52,539.52 1056.87,503.87 J8.WP@1056.87,385.15
  other v5: 9751.97,3488.19
  other v12: 1057.85,512.31
SDA: R9.2 U1.6 U4.5 | length 1126.5
  Bottom Layer w7.87: U4.5@7539.38,1378.75 7587.75,1378.75 7613.13,1404.13 7832.87,1404.13 7863,1374 7863,1197 R9.2@7883,1177 7909,1203 7909,1382 7858,1433 7673.16,1433 7629.84,1476.31 7626.89,1479.27 U1.6@7590.47,1479.27
SDRAM_FEEDBACK: NT3.1 U5.AF14 | length 1733.5
  Top Layer w5: v1(9968.5,2728.35) 10000,2728.35 10007.87,2736.22 U5.AF14@10007.87,2952.76
  MidLayer1 w5: v5(10114.17,2248.03) 10114.17,1795.28 10204.72,1704.73 10389.76,1704.73 10452.76,1641.73 NT3.1@10452.76,1562.99
  MidLayer2 w5: v1(9968.5,2728.35) 10114.17,2582.68 v5(10114.17,2248.03)
SFLASH.DIN: U5.D22 U20.5 U21.5 | length 1113.8
  Top Layer w5: v1(10350.39,4334.65) U20.5@10509.84,4334.65 ; v1(10370.08,4583.07) U21.5@10509.84,4583.07
  Top Layer w7.87: U5.D22@10322.83,3818.9 v1(10342.52,3838.58)
  MidLayer1 w5: v1(10342.52,3838.58) 10362.2,3858.27 10362.2,3893.7 10387.68,3919.17 10387.68,4013.9 10350.39,4051.18 v1(10350.39,4334.65) 10350.39,4563.39 v1(10370.08,4583.07)
SFLASH.DOUT: U5.D20 U20.2 U21.2 | length 1205.6
  Top Layer w5: v1(10090.55,4649.61) 10114.17,4649.61 10145.67,4681.1 U21.2@10234.25,4681.1 U21.2@10232.28,4683.07 ; v1(10125.98,4434.65) U20.2@10208.66,4434.65
  Top Layer w7.87: U5.D20@10244.09,3818.9 v1(10263.78,3838.58)
  MidLayer1 w5: v1(10090.55,4649.61) 10103.68,4636.48 10103.68,4456.95 v1(10125.98,4434.65) ; v1@10125.98,4433.07 v1(10125.98,4434.65) ; v1(10263.78,3838.58) 10283.46,3858.27 10283.46,4000 10283.46,4019.69 10292.73,4028.95 10292.73,4314.41 10172.49,4434.65 v1(10125.98,4434.65)
SFLASH.FLASH1_CS_N: U5.D21 U21.1 | length 1149
  Top Layer w5: v1(10090.55,4685.04) 10090.55,4704.73 10118.9,4733.07 U21.1@10208.66,4733.07
  Top Layer w7.87: U5.D21@10283.46,3818.9 v1(10303.15,3838.58)
  MidLayer1 w5: v1(10090.55,4685.04) 10125.98,4685.04 10153.54,4657.48 10153.54,4488.59 10322.83,4319.3 10322.83,4019.69 10322.83,4000 10322.83,3858.27 v1(10303.15,3838.58)
SFLASH.FLASH2_CS_N: U5.C21 U20.1 | length 799.8
  Top Layer w5: v1(10125.98,4484.65) U20.1@10208.66,4484.65
  Top Layer w7.87: U5.C21@10283.46,3858.27 v1(10303.15,3877.95)
  MidLayer1 w5: v1(10125.98,4484.65) 10141.74,4484.65 10303.15,4323.23 10303.15,4019.69 10303.15,4000 v1(10303.15,3877.95)
SFLASH.SCLK: U5.C23 U20.6 U21.6 | length 1220.5
  Top Layer w5: v1(10338.58,4582.68) 10338.58,4614.17 10357.48,4633.07 U21.6@10509.84,4633.07 ; v1(10370.08,4384.65) U20.6@10505,4384.65
  Top Layer w7.87: U5.C23@10362.2,3858.27 v1(10381.89,3877.95)
  MidLayer1 w5: v1(10338.58,4582.68) 10338.58,4606.3 10346.46,4614.17 10385.83,4614.17 10393.7,4606.3 10393.7,4408.27 v1(10370.08,4384.65) 10370.08,4056.6 10404.68,4022 10404.68,4010.98 10404.68,3992.96 10404.68,3900.75 v1(10381.89,3877.95)
SHIELD: C271.1 J4.5 J4.6 J5.MH1 J5.MH2 J5.MH3 J6.MH1 J6.MH2 J6.MH3 J7.10 J7.11 J8.S1 J8.S2 J8.S3 J8.S4 J8.S5 J8.S6 J9.10 J9.11 R317.1 SW6.S1 SW6.S2 | length 4027.9
  MidLayer1 w70: v4@7336.08,5182.23 7420.3,5182.23 7493.19,5255.12 7493.19,5801.86 J4.5@7781.89,6090.55
  Bottom Layer w17: J8.S6@1126.56,1323.34 1126.56,1192.34 1169.29,1149.61 2063.56,1149.61 ; 1488.76,1150.18 J8.S5@1488.76,1337.11 ; 1789.94,1151 J8.S4@1789.94,1337.11 ; J8.S3@2063.56,1409.95 2063.56,1149.61 ; J8.S1@2129.7,266.25 2129.7,775.81 2063.56,841.95 2063.56,1149.61 ; R317.1@7431.67,5284.64 v4(7488.65,5284.64) ; R317.1@7431.67,5329.55 v4(7488.65,5329.55)
  Bottom Layer w23.62: C271.1@7345.88,5109.24 v4(7345.88,5180.11) ; C271.1@7401,5109.24 v4(7401,5180.11)
  other v1: 10122.54,113 10171,113 10222.54,113 10271,113 10322.54,113 10371,113 10422.54,113 10471,113 10122.53,159.54 10471,159.54 10122.54,202 10171,202 10222.54,202 10271,202 10322.54,202 10371,202 10422.54,202 10471,202
  other v2: 838.68,208.45 878.68,208.45 918.68,208.45 963.68,208.45
  other v6: 5017,6156 5049.48,6156 5081.96,6156 5114.44,6156 5146.92,6156 6126.65,6156 6159.13,6156 6191.61,6156 6224.09,6156 6256.57,6156 6388.21,6156 6420.69,6156 6453.17,6156 6485.65,6156 6518.13,6156 7497.86,6156 7530.34,6156 7562.82,6156 7595.3,6156 7627.78,6156 5017,6188.48 5146.92,6188.48 6126.65,6188.48 6256.57,6188.48 6388.21,6188.48 6518.13,6188.48 7497.86,6188.48 7627.78,6188.48 5017,6220.96 5146.92,6220.96 6126.65,6220.96 6256.57,6220.96 6388.21,6220.96 6518.13,6220.96 7497.86,6220.96 7627.78,6220.96 5017,6253.44 5146.92,6253.44 6126.65,6253.44 6256.57,6253.44 6388.21,6253.44 6518.13,6253.44 7497.86,6253.44 7627.78,6253.44 5017,6285.92 5049.48,6285.92 6224.09,6285.92 6256.57,6285.92 6388.21,6285.92 6420.69,6285.92 7595.3,6285.92 7627.78,6285.92
SPK.SPK_L+: J15.8 U17.15 | length 2228.8
  Top Layer w30: v4(5805.51,4994.27) v4(5805.51,5039.19)
  MidLayer1 w30: v4(5805.51,4994.27) v4(5805.51,5039.19)
  MidLayer2 w30: v4(5805.51,4994.27) v4(5805.51,5039.19)
  MidLayer4 w30: v4(5805.51,4994.27) v4(5805.51,5039.19)
  MidLayer3 w23.62: v1(4318.9,5226.38) 4769.62,5226.38 5108.4,4887.6 5756.92,4887.6 5805.51,4936.19 v4(5805.51,4994.27)
  MidLayer3 w30: v4(5805.51,4994.27) v4(5805.51,5039.19)
  Bottom Layer w11.81: U17.15@4236.22,5212.6 4289.37,5212.6 4303.15,5226.38 v1(4318.9,5226.38)
  Bottom Layer w50: J15.8@5805.51,4838.98 v4@5805.51,5049.69
SPK.SPK_L-: C177.1 J15.7 U17.17 | length 2592.4
  Top Layer w30: v4(5805.51,4538.77) v4(5805.51,4583.68)
  MidLayer1 w30: v4(5805.51,4538.77) v4(5805.51,4583.68)
  MidLayer2 w30: v4(5805.51,4538.77) v4(5805.51,4583.68)
  MidLayer4 w30: v4(5805.51,4538.77) v4(5805.51,4583.68)
  MidLayer3 w23.62: v1(4318.9,5147.64) 4354.33,5147.64 4383.86,5177.17 4763.83,5177.17 5282.2,4658.8 5783.21,4658.8 5805.51,4636.5 v4(5805.51,4583.68)
  MidLayer3 w30: v4(5805.51,4538.77) v4(5805.51,4583.68)
  Bottom Layer w15.75: U17.17@4236.22,5161.42 4289.37,5161.42 4303.15,5147.64 v1(4318.9,5147.64)
  Bottom Layer w23.62: v1(4318.9,5147.64) 4346.46,5147.64 4366.14,5167.32 4366.14,5271.14 4385.38,5290.38 C177.1@4492.05,5290.38
  Bottom Layer w50: v4@5805.51,4528.27 J15.7@5805.51,4738.98
SPK.SPK_R+: J15.3 U17.28 | length 2655.7
  Top Layer w30: v4@6005.51,4538.77 v4@6005.51,4583.68
  MidLayer1 w30: v4@6005.51,4538.77 v4@6005.51,4583.68
  MidLayer2 w30: v4@6005.51,4538.77 v4@6005.51,4583.68
  MidLayer4 w30: v4@6005.51,4538.77 v4@6005.51,4583.68
  MidLayer3 w23.62: v1(4318.9,4866.14) 4303.15,4866.14 4283.46,4885.83 4283.46,5003.94 4303.15,5023.62 4377.95,5023.62 4405.51,4996.06 4868.31,4996.06 5373,4491.38 5956.61,4491.38 6004,4538.77 v4@6005.51,4538.77
  MidLayer3 w30: v4@6005.51,4538.77 v4@6005.51,4583.68
  Bottom Layer w11.81: U17.28@4236.22,4879.92 4289.37,4879.92 4303.15,4866.14 v1(4318.9,4866.14)
  Bottom Layer w50: v4@6005.48,4525.89 J15.3@6005.48,4736.6
  other v4: 6005.48,4536.39 6005.48,4581.3
SPK.SPK_R-: C180.1 J15.4 U17.26 | length 3297.7
  Top Layer w30: v4(6005.45,4994.27) v4(6005.45,5039.19)
  MidLayer1 w30: v4(6005.45,4994.27) v4(6005.45,5039.19)
  MidLayer2 w30: v4(6005.45,4994.27) v4(6005.45,5039.19)
  MidLayer4 w30: v4(6005.45,4994.27) v4(6005.45,5039.19)
  MidLayer3 w23.62: v1(4318.9,4944.88) 4868.12,4944.88 5350.24,4462.76 6004.69,4462.76 6052.47,4510.53 6052.47,4947.25 v4(6005.45,4994.27)
  MidLayer3 w30: v4(6005.45,4994.27) v4(6005.45,5039.19)
  Bottom Layer w11.81: U17.26@4236.22,4931.1 4289.37,4931.1 4303.15,4944.88 v1(4318.9,4944.88)
  Bottom Layer w23.62: v1(4318.9,4944.88) 4354.12,4944.88 4382,4917 4382,4790 4396.68,4775.32 C180.1@4492.05,4775.32
  Bottom Layer w50: J15.4@6005.51,4838.98 v4@6005.51,5049.69
SPK.VOL: C174.2 J15.1 U17.5 VR2.2 | length 11105.2
  Top Layer w30: v4(6105.51,4538.77) v4(6105.51,4583.68)
  MidLayer1 w30: v4(6105.51,4538.77) v4(6105.51,4583.68)
  MidLayer1 w31.5: VR2.2@791.34,539.37 791.34,790.8 748.68,833.45 748.68,2231.63 192.91,2787.4 189,2791.31 189,3574.83 240.67,3626.5 996.06,3626.5 1027.56,3657.99 1027.56,4314.96 1185.04,4472.44 2440.95,4472.44 2551.18,4582.68 2799.21,4582.68 v2(2854.33,4637.8)
  MidLayer2 w15.75: v4(4964.57,4677.17) 4986.83,4677.17 5163.1,4500.9 6067.65,4500.9 v4(6105.51,4538.77)
  MidLayer2 w30: v4(6105.51,4538.77) v4(6105.51,4583.68)
  MidLayer4 w30: v4(6105.51,4538.77) v4(6105.51,4583.68)
  MidLayer3 w15.75: 3850.39,4637.8 3881.89,4606.3 3918,4606.3 3971.7,4660 4775,4660 4792.17,4677.17 v4(4964.57,4677.17)
  MidLayer3 w23.62: v2(2854.33,4637.8) 3850.39,4637.8 3850.39,4952.76 3879.92,4982.28 v1(3921.26,4982.28)
  MidLayer3 w30: v4(6105.51,4538.77) v4(6105.51,4583.68)
  Bottom Layer w11.81: v1(3921.26,4982.28) U17.5@4003.94,4982.28
  Bottom Layer w15.75: v1(3850.39,4720.47) C174.2@3881.89,4720.47
  Bottom Layer w50: v4@6105.51,4528.27 J15.1@6105.51,4738.98
SRAM.A0: U5.J23 U22.1 U23.1 | length 1232.3
  Top Layer w5: U23.1@10862.2,3062.99 v1(10862.21,3114.17) ; U22.1@10862.2,3645.67 v1(10862.21,3696.85)
  Top Layer w7.87: U5.J23@10362.2,3622.05 v1(10381.89,3641.73)
  MidLayer1 w5: v1(10381.89,3641.73) 10401.58,3661.42 10543.31,3661.42 10562.99,3661.42 10744.09,3661.42 10779.53,3696.85 v1(10862.21,3696.85)
  MidLayer2 w5: v1(10862.21,3114.17) 10862.21,3401.58 10842.52,3421.26 10842.52,3677.17 v1(10862.21,3696.85)
SRAM.A1: U5.H24 U22.2 U23.2 | length 1265.2
  Top Layer w5: U23.2@10893.7,3062.99 v1(10893.7,3137.8) ; U22.2@10893.7,3645.67 v1(10893.7,3720.47)
  Top Layer w7.87: U5.H24@10401.58,3661.42 v1(10421.26,3681.1)
  MidLayer1 w5: v1(10421.26,3681.1) 10543.31,3681.1 10562.99,3681.1 10748.03,3681.1 10787.4,3720.47 v1(10893.7,3720.47)
  MidLayer2 w5: v1(10893.7,3137.8) 10893.7,3401.58 10874.02,3421.26 10874.02,3444.88 10881.89,3452.76 10881.89,3641.73 10893.7,3653.54 v1(10893.7,3720.47)
SRAM.A2: U5.J24 U22.3 U23.3 | length 1256
  Top Layer w5: U23.3@10925.2,3062.99 v1(10925.2,3114.17) ; U22.3@10925.2,3645.67 v1(10925.2,3696.85)
  Top Layer w7.87: U5.J24@10401.58,3622.05 v1(10421.26,3641.73)
  MidLayer1 w5: v1(10421.26,3641.73) 10543.31,3641.73 10562.99,3641.73 10740.16,3641.73 10775.59,3677.17 10905.51,3677.17 v1(10925.2,3696.85)
  MidLayer2 w5: v1(10925.2,3114.17) 10925.2,3433.07 10905.51,3452.76 10905.51,3618.11 10925.2,3637.8 v1(10925.2,3696.85)
SRAM.A3: U5.K24 U22.4 U23.4 | length 1374.6
  Top Layer w5: U23.4@10956.69,3062.99 v1(10956.7,3137.8) ; U22.4@10956.69,3645.67 v1(10956.69,3720.47)
  Top Layer w7.87: U5.K24@10401.58,3582.68 v1(10421.26,3602.36)
  MidLayer1 w5: v1(10421.26,3602.36) 10515.75,3602.36 10527.56,3614.17 10543.31,3614.17 10562.99,3614.17 10570.87,3614.17 10586.61,3629.92 10744.09,3629.92 10779.53,3665.36 10925.2,3665.36 10956.69,3696.85 v1(10956.69,3720.47)
  MidLayer2 w5: v1(10956.7,3137.8) 10956.7,3393.7 10937.01,3413.39 10937.01,3444.88 10944.88,3452.76 10944.88,3547.24 10956.69,3559.06 v1(10956.69,3720.47)
SRAM.A4: U5.K23 U22.5 U23.5 | length 1420.3
  Top Layer w5: U23.5@10988.19,3062.99 v1(10988.19,3114.17) ; U22.5@10988.19,3645.67 v1(10988.19,3696.85)
  Top Layer w7.87: U5.K23@10362.2,3582.68 v1(10381.89,3602.36)
  MidLayer1 w5: v1(10381.89,3602.36) 10401.58,3582.68 10515.75,3582.68 10527.56,3570.87 10543.31,3570.87 10562.99,3570.87 10594.49,3539.37 10681.1,3539.37 10795.28,3653.54 10944.88,3653.54 v1(10988.19,3696.85)
  MidLayer2 w5: v1(10988.19,3114.17) 10988.19,3393.7 10976.38,3405.51 10976.38,3444.88 10988.19,3456.69 v1(10988.19,3696.85)
SRAM.A5: U5.L19 U22.18 U23.18 | length 2135.1
  Top Layer w5: U23.18@11397.64,3062.99 v1(11397.64,3137.8) ; U22.18@11397.64,3645.67 v1(11397.64,3720.47)
  Top Layer w7.87: U5.L19@10204.72,3543.31 v1(10224.41,3562.99)
  MidLayer1 w5: v1(10224.41,3562.99) 10244.1,3582.68 10354.33,3582.68 10362.2,3574.8 10362.2,3515.75 10374.02,3503.94 10507.87,3503.94 10515.75,3496.06 10543.31,3496.06 10562.99,3496.06 10685.04,3496.06 10807.09,3618.11 10972.44,3618.11 11031.5,3677.17 11377.95,3677.17 11397.64,3696.85 v1(11397.64,3720.47)
  MidLayer2 w5: v1(11397.64,3137.8) 11397.64,3401.58 11377.95,3421.26 11377.95,3444.88 11385.83,3452.76 11385.83,3641.73 11397.64,3653.54 v1(11397.64,3720.47)
SRAM.A6: U5.N24 U22.19 U23.19 | length 1825.1
  Top Layer w5: U23.19@11429.13,3062.99 v1(11429.13,3114.17) ; U22.19@11429.13,3645.67 v1(11429.13,3696.85)
  Top Layer w7.87: U5.N24@10401.58,3464.57 v1(10421.26,3484.25)
  MidLayer1 w5: v1(10421.26,3484.25) 10543.31,3484.25 10562.99,3484.25 10688.98,3484.25 10811.02,3606.3 10976.38,3606.3 11035.43,3665.36 11397.64,3665.36 v1(11429.13,3696.85)
  MidLayer2 w5: v1(11429.13,3114.17) 11429.13,3433.07 11409.45,3452.76 11409.45,3618.11 11429.13,3637.8 v1(11429.13,3696.85)
SRAM.A7: U5.N23 U22.20 U23.20 | length 1980.9
  Top Layer w5: U23.20@11460.63,3062.99 v1(11460.63,3137.8) ; U22.20@11460.63,3645.67 v1(11460.63,3720.47)
  Top Layer w7.87: U5.N23@10362.2,3464.57 v1(10381.89,3484.25)
  MidLayer1 w5: v1(10381.89,3484.25) 10401.58,3464.57 10433.07,3464.57 10440.95,3472.44 10543.31,3472.44 10562.99,3472.44 10692.91,3472.44 10814.96,3594.49 10980.32,3594.49 11039.37,3653.54 11413.39,3653.54 11460.63,3700.79 v1(11460.63,3720.47)
  MidLayer2 w5: v1(11460.63,3137.8) 11460.63,3393.7 11440.95,3413.39 11440.95,3444.88 11448.82,3452.76 11448.82,3547.24 11460.63,3559.06 v1(11460.63,3720.47)
SRAM.A8: U5.P23 U22.21 U23.21 | length 1966.6
  Top Layer w5: U23.21@11492.13,3062.99 v1(11492.13,3114.17) ; U22.21@11492.13,3645.67 v1(11492.13,3696.85)
  Top Layer w7.87: U5.P23@10362.2,3425.2 v1(10381.89,3405.51)
  MidLayer1 w5: v1(10381.89,3405.51) 10401.58,3425.2 10433.07,3425.2 10440.95,3417.32 10543.31,3417.32 10562.99,3417.32 10653.54,3417.32 10818.9,3582.68 10984.25,3582.68 11043.31,3641.73 11437.01,3641.73 v1(11492.13,3696.85)
  MidLayer2 w5: v1(11492.13,3114.17) 11492.13,3393.7 11480.32,3405.51 11480.32,3444.88 11472.44,3452.76 11472.44,3531.5 11484.25,3543.31 11484.25,3622.05 11492.13,3629.92 v1(11492.13,3696.85)
SRAM.A9: U5.P24 U22.22 U23.22 | length 2026.4
  Top Layer w5: U23.22@11523.62,3062.99 v1(11523.62,3137.8) ; U22.22@11523.62,3645.67 v1(11523.62,3720.47)
  Top Layer w7.87: U5.P24@10401.58,3425.2 v1(10421.26,3405.51)
  MidLayer1 w5: v1(10421.26,3405.51) 10543.31,3405.51 10562.99,3405.51 10657.48,3405.51 10822.83,3570.87 10988.19,3570.87 11047.24,3629.92 11456.69,3629.92 11523.62,3696.85 v1(11523.62,3720.47)
  MidLayer2 w5: v1(11523.62,3137.8) 11523.62,3401.58 11500,3425.2 11500,3440.95 11511.81,3452.76 11511.81,3531.5 11523.62,3543.31 v1(11523.62,3720.47)
SRAM.A10: U5.H23 U22.23 U23.23 | length 2058.4
  Top Layer w5: v1(11523.62,3437.01) U23.23@11523.62,3511.81 ; v1(11523.62,4019.69) U22.23@11523.62,4094.49
  Top Layer w7.87: U5.H23@10362.2,3661.42 v1(10381.89,3681.1)
  MidLayer1 w5: v1(10381.89,3681.1) 10401.58,3700.79 10543.31,3700.79 10562.99,3700.79 10751.97,3700.79 10795.28,3744.1 11248.03,3744.1 v1(11523.62,4019.69)
  MidLayer2 w5: v1(11523.62,3437.01) 11523.62,3507.87 11543.31,3527.56 11543.31,3736.22 11523.62,3755.91 v1(11523.62,4019.69)
SRAM.A11: U5.G23 U22.24 U23.24 | length 1987
  Top Layer w5: v1(11492.13,3460.63) U23.24@11492.13,3511.81 ; v1(11492.13,4043.31) U22.24@11492.13,4094.49
  Top Layer w7.87: U5.G23@10362.2,3700.79 v1(10381.89,3720.47)
  MidLayer1 w5: v1(10381.89,3720.47) 10401.58,3740.16 10543.31,3740.16 10562.99,3740.16 10582.68,3740.16 10598.43,3755.91 11228.35,3755.91 11492.13,4019.69 v1(11492.13,4043.31)
  MidLayer2 w5: v1(11492.13,3460.63) 11492.13,3527.56 11503.94,3539.37 11503.94,3618.11 11511.81,3625.99 11511.81,3704.73 11492.13,3724.41 v1(11492.13,4043.31)
SRAM.A12: U5.F24 U22.25 U23.25 | length 1923.4
  Top Layer w5: v1(11460.63,3437.01) U23.25@11460.63,3511.81 ; v1(11460.63,4019.69) U22.25@11460.63,4094.49
  Top Layer w7.87: U5.F24@10401.58,3740.16 v1(10421.26,3759.84)
  MidLayer1 w5: v1(10421.26,3759.84) 10543.31,3759.84 10562.99,3759.84 10586.61,3759.84 10594.49,3767.72 11208.66,3767.72 11320.43,3879.49 v1(11460.63,4019.69)
  MidLayer2 w5: v1(11460.63,3437.01) 11460.63,3539.37 11472.44,3551.18 11472.44,3704.73 11480.32,3712.6 11480.32,3736.22 11460.63,3755.91 v1(11460.63,4019.69)
SRAM.A13: U5.F23 U22.26 U23.26 | length 1907.7
  Top Layer w5: v1(11429.13,3460.63) U23.26@11429.13,3511.81 ; v1(11429.13,4043.31) U22.26@11429.13,4094.49
  Top Layer w7.87: U5.F23@10362.2,3740.16 v1(10381.89,3759.84)
  MidLayer1 w5: v1(10381.89,3759.84) 10401.58,3779.53 10543.31,3779.53 10562.99,3779.53 11188.98,3779.53 11429.13,4019.69 v1(11429.13,4043.31)
  MidLayer2 w5: v1(11429.13,3460.63) 11429.13,3606.3 11448.82,3625.99 11448.82,3704.73 11429.13,3724.41 v1(11429.13,4043.31)
SRAM.A14: U5.E24 U22.27 U23.27 | length 1844.1
  Top Layer w5: v1(11397.64,3437.01) U23.27@11397.64,3511.81 ; v1(11397.64,4019.69) U22.27@11397.64,4094.49
  Top Layer w7.87: U5.E24@10401.58,3779.53 v1(10421.26,3799.21)
  MidLayer1 w5: v1(10421.26,3799.21) 10543.31,3799.21 10562.99,3799.21 11177.17,3799.21 v1(11397.64,4019.69)
  MidLayer2 w5: v1(11397.64,3437.01) 11397.64,3629.92 11409.45,3641.73 11409.45,3704.73 11417.32,3712.6 11417.32,3736.22 11397.64,3755.91 v1(11397.64,4019.69)
SRAM.A15: U5.T23 U22.42 U23.42 | length 1351.6
  Top Layer w5: v1(10925.2,3460.63) U23.42@10925.2,3511.81 ; v1(10925.2,4043.31) U22.42@10925.2,4094.49
  Top Layer w7.87: U5.T23@10362.2,3346.46 v1(10381.89,3326.77)
  MidLayer1 w5: v1(10381.89,3326.77) 10401.58,3346.46 10515.75,3346.46 10527.56,3334.65 10549.97,3334.65 10584.78,3369.45 10672.6,3369.45 10720.47,3417.32 10905.51,3417.32 10925.2,3437.01 v1(10925.2,3460.63)
  MidLayer2 w5: v1(10925.2,3460.63) 10925.2,3606.3 10944.88,3625.99 10944.88,3704.73 10925.2,3724.41 v1(10925.2,4043.31)
SRAM.A16: U5.R24 U22.43 U23.43 | length 1278.2
  Top Layer w5: v1(10893.7,3437.01) U23.43@10893.7,3511.81 ; v1(10893.7,4019.69) U22.43@10893.7,4094.49
  Top Layer w7.87: U5.R24@10401.58,3385.83 v1(10421.26,3366.14)
  MidLayer1 w5: v1(10421.26,3366.14) 10515.75,3366.14 10531.5,3381.89 10543.31,3381.89 10562.99,3381.89 10665.35,3381.89 10720.47,3437.01 v1(10893.7,3437.01)
  MidLayer2 w5: v1(10893.7,3437.01) 10893.7,3629.92 10905.51,3641.73 10905.51,3704.73 10913.39,3712.6 10913.39,3736.22 10893.7,3755.91 v1(10893.7,4019.69)
SRAM.A17: U5.T19 U22.44 U23.44 | length 1473.3
  Top Layer w5: v1(10862.21,3460.63) U23.44@10862.21,3511.81 ; v1(10862.21,4043.31) U22.44@10862.21,4094.49
  Top Layer w7.87: U5.T19@10204.72,3346.46 v1(10224.41,3326.77)
  MidLayer1 w5: v1(10224.41,3326.77) 10244.1,3307.09 10354.33,3307.09 10362.2,3314.96 10362.2,3374.02 10374.02,3385.83 10507.87,3385.83 10515.75,3393.7 10543.31,3393.7 10562.99,3393.7 10661.42,3393.7 10728.35,3460.63 v1(10862.21,3460.63)
  MidLayer2 w5: v1(10862.21,3460.63) 10862.21,3649.61 10881.89,3669.29 10881.89,3704.73 10862.21,3724.41 v1(10862.21,4043.31)
SRAM.A18: U5.E23 U22.28 U23.28 | length 1850.9
  Top Layer w5: v1(11366.14,3460.63) U23.28@11366.14,3511.81 ; v1(11366.14,4043.31) U22.28@11366.14,4094.49
  Top Layer w7.87: U5.E23@10362.2,3779.53 v1(10381.89,3799.21)
  MidLayer1 w5: v1(10381.89,3799.21) 10401.58,3818.9 10437.01,3818.9 10456.69,3838.58 10543.47,3838.58 10570.6,3811.45 10738.53,3811.45 10765.66,3838.58 11185.04,3838.58 11366.14,4019.69 v1(11366.14,4043.31)
  MidLayer2 w5: v1(11366.14,3460.63) 11366.14,3649.61 11385.83,3669.29 11385.83,3704.73 11366.14,3724.41 v1(11366.14,4043.31)
SRAM.D0: U5.M25 U22.7 | length 854.8
  Top Layer w5: U5.M25@10440.95,3503.94 10460.63,3523.62 10507.87,3523.62 10519.69,3511.81 10543.31,3511.81 10562.99,3511.81 10673.23,3511.81 10700.79,3539.37 10700.79,3618.11 10826.77,3744.1 11035.43,3744.1 11051.18,3728.35 U22.7@11051.18,3645.67
SRAM.D1: U5.L26 U22.8 | length 841
  Top Layer w5: U5.L26@10480.32,3543.31 10507.87,3543.31 10515.75,3551.18 10543.31,3551.18 10562.99,3551.18 10586.61,3527.56 10657.48,3527.56 10688.98,3559.06 10688.98,3622.05 10822.83,3755.91 11055.12,3755.91 11082.68,3728.35 U22.8@11082.68,3645.67
SRAM.D2: U5.L25 U22.9 | length 921.6
  Top Layer w5: U5.L25@10440.95,3543.31 10460.63,3562.99 10543.31,3562.99 10562.99,3562.99 10570.87,3562.99 10594.49,3539.37 10653.54,3539.37 10677.17,3562.99 10677.17,3625.98 10818.9,3767.72 11074.8,3767.72 11114.17,3728.35 U22.9@11114.17,3645.67
SRAM.D3: U5.K26 U22.10 | length 871.1
  Top Layer w5: U5.K26@10480.32,3582.68 10507.87,3582.68 10515.75,3574.8 10543.31,3574.8 10562.99,3574.8 10574.8,3586.61 10574.8,3610.24 10598.43,3633.86 10669.29,3633.86 10814.96,3779.53 11094.49,3779.53 11145.67,3728.35 U22.10@11145.67,3645.67
SRAM.D4: U5.K25 U22.13 | length 994.4
  Top Layer w5: U5.K25@10440.95,3582.68 10460.63,3602.36 10515.75,3602.36 10527.56,3614.17 10543.31,3614.17 10562.99,3614.17 10598.11,3649.29 10668.98,3649.29 10811.02,3791.34 11177.17,3791.34 11240.16,3728.35 U22.13@11240.16,3645.67
SRAM.D5: U5.J25 U22.14 | length 1019.4
  Top Layer w5: U5.J25@10440.95,3622.05 10460.63,3641.73 10543.31,3641.73 10562.99,3641.73 10570.87,3641.73 10588.43,3659.29 10659.29,3659.29 10803.15,3803.15 11196.85,3803.15 11271.65,3728.35 U22.14@11271.65,3645.67
SRAM.D6: U5.H26 U22.15 | length 1005
  Top Layer w5: U5.H26@10480.32,3661.42 10543.31,3661.42 10562.99,3661.42 10570.87,3669.29 10653.54,3669.29 10669.29,3685.04 10799.21,3814.96 11216.54,3814.96 11303.15,3728.35 U22.15@11303.15,3645.67
SRAM.D7: U5.H25 U22.16 | length 1085.6
  Top Layer w5: U5.H25@10440.95,3661.42 10460.63,3681.1 10543.31,3681.1 10562.99,3681.1 10649.61,3681.1 10795.28,3826.77 11236.22,3826.77 11334.65,3728.35 U22.16@11334.65,3645.67
SRAM.D8: U5.G26 U22.29 | length 1068.1
  Top Layer w5: U5.G26@10480.32,3700.79 10543.31,3700.79 10562.99,3700.79 10653.54,3700.79 10846.46,3893.7 11220.47,3893.7 11334.65,4007.87 U22.29@11334.65,4094.49
SRAM.D9: U5.G25 U22.30 | length 1076
  Top Layer w5: U5.G25@10440.95,3700.79 10460.63,3720.47 10496.06,3720.47 10515.75,3740.16 10543.31,3740.16 10562.99,3740.16 10676.39,3740.16 10841.74,3905.51 11200.79,3905.51 11303.15,4007.87 U22.30@11303.15,4094.49
SRAM.D10: U5.F26 U22.31 | length 988.8
  Top Layer w5: U5.F26@10480.32,3740.16 10500,3740.16 10515.75,3755.91 10543.31,3755.91 10562.99,3755.91 10676.13,3755.91 10837.55,3917.32 11181.1,3917.32 11271.65,4007.87 U22.31@11271.65,4094.49
SRAM.D11: U5.F25 U22.32 | length 996.7
  Top Layer w5: U5.F25@10440.95,3740.16 10460.63,3759.84 10500,3759.84 10511.81,3771.65 10543.31,3771.65 10562.99,3771.65 10675.95,3771.65 10833.43,3929.13 11161.42,3929.13 11240.16,4007.87 U22.32@11240.16,4094.49
SRAM.D12: U5.E26 U22.35 | length 846.6
  Top Layer w5: U5.E26@10480.32,3779.53 10500,3779.53 10507.87,3787.4 10543.31,3787.4 10562.99,3787.4 10677.12,3787.4 10830.67,3940.95 11078.74,3940.95 11145.67,4007.87 U22.35@11145.67,4094.49
SRAM.D13: U5.E25 U22.36 | length 854.4
  Top Layer w5: U5.E25@10440.95,3779.53 10460.63,3799.21 10543.31,3799.21 10562.99,3799.21 10664.44,3799.21 10817.98,3952.76 11059.05,3952.76 11114.17,4007.88 U22.36@11114.17,4094.49
SRAM.D14: U5.D26 U22.37 | length 795.3
  Top Layer w5: U5.D26@10480.32,3818.9 10500,3818.9 10524.39,3843.29 10546.38,3843.29 10580.21,3809.45 10658.68,3809.45 10813.8,3964.57 11039.37,3964.57 11082.68,4007.87 U22.37@11082.68,4094.49
SRAM.D15: U5.D25 U22.38 | length 838.3
  Top Layer w5: U5.D25@10440.95,3818.9 10460.63,3838.58 10500,3838.58 10516.33,3854.91 10553.22,3854.91 10586.68,3821.45 10652.72,3821.45 10673.07,3841.8 10807.65,3976.38 11019.68,3976.38 11051.18,4007.87 ; 11051.18,4043.31 11051.18,4007.87 ; U22.38@11051.18,4094.49 11051.18,4007.88
SRAM.D16: U5.AA25 U23.7 | length 730.4
  Top Layer w5: U5.AA25@10440.95,3149.61 10460.63,3129.92 10500,3129.92 10511.81,3118.11 10543.31,3118.11 10562.99,3118.11 10811.02,3118.11 10854.33,3161.42 11035.43,3161.42 11051.18,3145.67 U23.7@11051.18,3062.99
SRAM.D17: U5.AA26 U23.8 | length 719.3
  Top Layer w5: U5.AA26@10480.32,3149.61 10500,3149.61 10515.75,3133.86 10543.31,3133.86 10562.99,3133.86 10807.09,3133.86 10846.46,3173.23 11055.12,3173.23 11082.68,3145.67 U23.8@11082.68,3062.99
SRAM.D18: U5.Y25 U23.9 | length 803.2
  Top Layer w5: U5.Y25@10440.95,3188.98 10460.63,3169.29 10496.06,3169.29 10515.75,3149.61 10543.31,3149.61 10562.99,3149.61 10803.15,3149.61 10838.58,3185.04 11074.8,3185.04 11114.17,3145.67 U23.9@11114.17,3062.99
